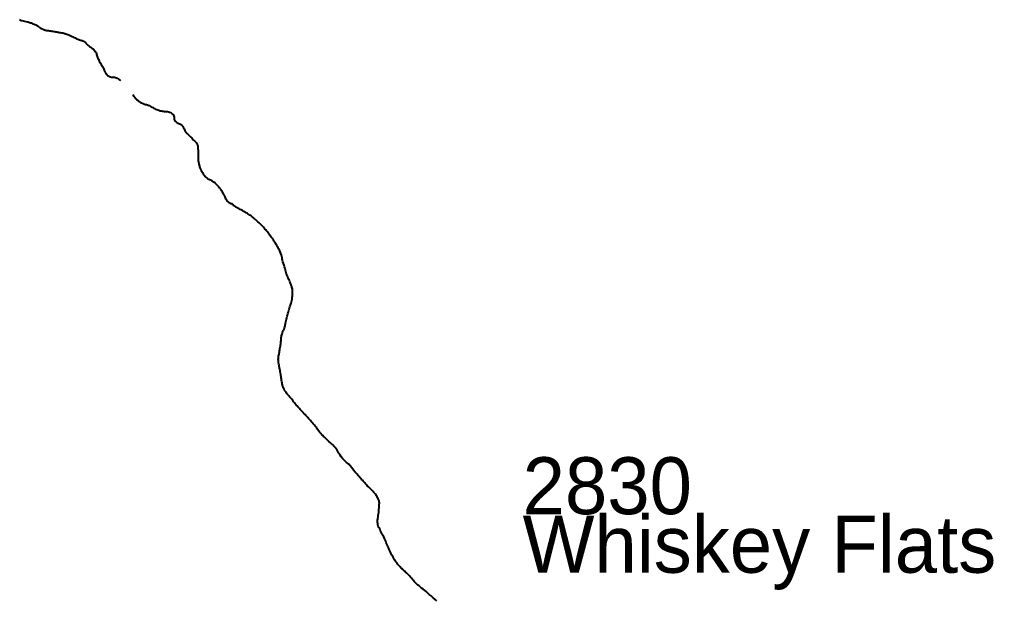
# Model space of a CAD drawing. Extents: x 322505 to 642419, y 5806860 to 5919753.
# Drawn here: x 604345 to 610335, y 5874702 to 5878274 of the extents above; entities that cross this region are included whole.
import ezdxf

# ---------------------------------------------------------------- set-up
doc = ezdxf.new("R2010")
doc.units = 0
doc.header["$LTSCALE"] = 140
for name, color, linetype, lineweight in [('1', 7, 'Continuous', 40), ('4', 7, 'Continuous', 40), ('5', 7, 'Continuous', 40)]:
    doc.layers.add(name, color=color, linetype=linetype, lineweight=lineweight)

msp = doc.modelspace()

# ---------------------------------------------------------------- linework, layer by layer
at = {"layer": '4'}
msp.add_lwpolyline([(604345, 5878274), (604349, 5878271), (604352, 5878270), (604356, 5878268), (604359.5, 5878267)], dxfattribs=at)
at = {"layer": '5'}
for points in [[(604360, 5878267), (604392, 5878260), (604395, 5878259), (604399, 5878259), (604403, 5878258), (604407, 5878256), (604413, 5878254), (604418, 5878253), (604422, 5878251), (604426, 5878250), (604430, 5878248), (604435, 5878246), (604440, 5878244), (604445, 5878241), (604451, 5878238), (604456, 5878234), (604459, 5878232), (604464, 5878228), (604469, 5878225), (604474, 5878221), (604480, 5878218), (604485, 5878216), (604490, 5878213), (604494, 5878212), (604498, 5878210), (604502, 5878209), (604507, 5878208), (604513, 5878207), (604519, 5878207), (604524, 5878206), (604530, 5878205), (604537, 5878204), (604543, 5878203), (604549, 5878202), (604556, 5878201), (604563, 5878200), (604569, 5878199), (604575, 5878198), (604580, 5878197), (604584, 5878196), (604589, 5878195), (604595, 5878194), (604603, 5878192), (604611, 5878191), (604618, 5878189), (604619, 5878188.5)], [(604619, 5878188.5), (604626, 5878187), (604631, 5878185), (604637, 5878183), (604643, 5878182), (604649, 5878179), (604656, 5878176), (604665, 5878172), (604673, 5878168), (604680, 5878164), (604687, 5878161), (604693, 5878158), (604698, 5878155), (604703, 5878153), (604709, 5878151), (604714, 5878149), (604720, 5878147), (604724, 5878146), (604727, 5878145), (604731, 5878144), (604735, 5878142), (604739, 5878140), (604745, 5878136), (604750, 5878132), (604754, 5878128), (604758, 5878124), (604761, 5878121), (604764, 5878118), (604768, 5878114), (604773, 5878110), (604778, 5878106), (604782, 5878103), (604788, 5878100), (604793, 5878096), (604798, 5878093), (604803, 5878089), (604807, 5878083), (604811, 5878078), (604813, 5878073), (604816, 5878068), (604818, 5878063), (604819, 5878059), (604821, 5878053), (604823, 5878047), (604825, 5878041), (604827, 5878036), (604830, 5878030), (604833, 5878024), (604836, 5878018), (604840, 5878012), (604844, 5878006), (604848, 5877998), (604852, 5877991), (604856, 5877985), (604858, 5877979), (604861, 5877974), (604863, 5877968), (604866, 5877962), (604869, 5877956), (604872, 5877949), (604876, 5877943), (604880, 5877937), (604883, 5877933), (604887, 5877930), (604891, 5877927), (604897, 5877924), (604904, 5877922), (604911, 5877920), (604918, 5877919), (604924, 5877919), (604930, 5877919), (604935, 5877918), (604941, 5877916), (604946, 5877913), (604952, 5877910), (604957, 5877906), (604962, 5877902), (604966, 5877898)], [(605041.8, 5877812.5), (605045, 5877808), (605048, 5877803), (605051, 5877798), (605054, 5877794), (605057, 5877790), (605060, 5877788), (605062, 5877785), (605065, 5877783), (605068, 5877780), (605072, 5877778), (605075, 5877774), (605079, 5877771), (605084, 5877767), (605089, 5877764), (605096, 5877761), (605105, 5877757), (605113, 5877754), (605120, 5877752), (605126, 5877751), (605132, 5877749), (605137, 5877747), (605143, 5877745), (605149, 5877742), (605155, 5877738), (605161, 5877735), (605167, 5877732), (605171, 5877728), (605177, 5877726), (605182, 5877723), (605189, 5877720), (605196, 5877718), (605201, 5877716), (605206, 5877714), (605211, 5877713), (605216, 5877712), (605220, 5877712), (605225, 5877711), (605231, 5877710), (605237, 5877709), (605242, 5877709), (605249, 5877709), (605255, 5877708), (605262, 5877707), (605268, 5877705), (605275, 5877702), (605280, 5877699), (605284, 5877695), (605288, 5877692), (605291, 5877689), (605293, 5877686), (605294, 5877683), (605295, 5877680), (605296, 5877673), (605297, 5877665), (605297, 5877660), (605299, 5877656), (605301, 5877652), (605305, 5877648), (605309, 5877644), (605312, 5877641), (605315, 5877639), (605318, 5877637), (605321, 5877636), (605325, 5877635), (605329, 5877633), (605332, 5877632), (605336, 5877630), (605340, 5877628), (605343, 5877625), (605346, 5877621), (605349, 5877617), (605351, 5877613), (605354, 5877607), (605357, 5877602), (605359, 5877597), (605361, 5877593), (605362, 5877589), (605364, 5877586), (605367, 5877582), (605371, 5877578), (605375, 5877573), (605380, 5877569), (605384, 5877564), (605389, 5877560), (605394, 5877555), (605399, 5877551), (605404, 5877546), (605410, 5877540), (605416, 5877533), (605421, 5877528), (605426, 5877523), (605431, 5877518), (605434, 5877513), (605437, 5877510), (605438, 5877505), (605440, 5877501), (605441, 5877496), (605442, 5877492), (605442, 5877479), (605443, 5877470)], [(605443, 5877470), (605443, 5877464), (605443, 5877458), (605443, 5877451), (605443, 5877445), (605443, 5877437), (605443, 5877429), (605443, 5877422), (605444, 5877414), (605444, 5877408), (605444, 5877403), (605445, 5877399), (605445, 5877395), (605447, 5877390), (605448, 5877384), (605449, 5877379), (605451, 5877373), (605453, 5877368), (605454, 5877363), (605457, 5877358), (605459, 5877353), (605463, 5877346), (605466, 5877340), (605470, 5877334), (605473, 5877329), (605475, 5877325), (605478, 5877320), (605482, 5877314), (605487, 5877309), (605493, 5877303), (605499, 5877298), (605504, 5877295), (605509, 5877293), (605514, 5877290), (605519, 5877288), (605525, 5877285), (605529, 5877282), (605534, 5877279), (605538, 5877277), (605541, 5877274), (605544, 5877273), (605547, 5877270), (605551, 5877266), (605555, 5877262), (605560, 5877256), (605564, 5877252), (605568, 5877247), (605572, 5877242), (605576, 5877238), (605580, 5877233), (605584, 5877228), (605588, 5877222), (605592, 5877215), (605595, 5877209), (605598, 5877203), (605600, 5877199), (605602, 5877195), (605605, 5877190), (605607, 5877184), (605610, 5877178), (605613, 5877172), (605615, 5877168), (605618, 5877164), (605620, 5877160), (605624, 5877157), (605628, 5877153), (605631, 5877151), (605635, 5877148), (605638, 5877146), (605641, 5877145), (605644, 5877143), (605647, 5877142), (605652, 5877143)], [(605865, 5876974), (605860, 5876981), (605854, 5876986), (605850, 5876992), (605845, 5876997), (605839, 5877003), (605834, 5877009), (605827, 5877016), (605819, 5877023), (605811, 5877031), (605803, 5877038), (605796, 5877044), (605790, 5877049), (605782, 5877056), (605776, 5877061), (605769, 5877066), (605762, 5877071), (605756, 5877075), (605750, 5877079), (605745, 5877083), (605739, 5877086), (605732, 5877090), (605725, 5877094), (605716, 5877099), (605709, 5877103), (605702, 5877106), (605696, 5877109), (605691, 5877112), (605685, 5877115), (605681, 5877118), (605676, 5877121), (605669, 5877126), (605663, 5877129), (605661, 5877132), (605658, 5877135), (605655, 5877138), (605652, 5877143)], [(605956, 5876324), (605957, 5876329), (605958, 5876335), (605960, 5876342), (605963, 5876350), (605964, 5876355), (605966, 5876359), (605968, 5876363), (605970, 5876367), (605972, 5876371), (605974, 5876378), (605976, 5876385), (605978, 5876391), (605979, 5876397), (605980, 5876402), (605981, 5876408), (605983, 5876415), (605985, 5876423), (605987, 5876432), (605989, 5876442), (605991, 5876450), (605994, 5876457), (605995, 5876464), (605998, 5876470), (606000, 5876477), (606002, 5876485), (606004, 5876493), (606006, 5876500), (606008, 5876507), (606010, 5876513), (606011, 5876517), (606013, 5876523), (606015, 5876530), (606018, 5876538), (606019, 5876546), (606021, 5876554), (606021, 5876560), (606022, 5876566), (606023, 5876572), (606023, 5876578), (606023, 5876584), (606023, 5876590), (606024, 5876596), (606024, 5876601), (606024, 5876605), (606024, 5876613), (606023, 5876617), (606022, 5876622), (606020, 5876628), (606019, 5876632), (606017, 5876636), (606016, 5876639), (606015, 5876643), (606014, 5876646), (606011, 5876654), (606008, 5876662), (606005, 5876669), (606002, 5876675), (606000, 5876680), (605998, 5876685), (605995, 5876690), (605992, 5876697), (605989, 5876705), (605985, 5876714), (605982, 5876725), (605980, 5876733), (605978, 5876740), (605976, 5876747), (605974, 5876754), (605972, 5876763), (605968, 5876774), (605965, 5876784), (605963, 5876793), (605961, 5876802), (605960, 5876809), (605958, 5876817), (605956, 5876826), (605953, 5876835), (605949, 5876846), (605944, 5876856), (605940, 5876863), (605936, 5876871), (605932, 5876877), (605927, 5876884), (605924, 5876890), (605921, 5876895), (605918, 5876901), (605916, 5876905), (605913, 5876910), (605910, 5876914), (605907, 5876918), (605903, 5876924), (605899, 5876929), (605893, 5876936), (605889, 5876942), (605885, 5876948), (605882, 5876953), (605878, 5876957), (605875, 5876962), (605870, 5876968), (605865, 5876974)], [(606226, 5875700), (606220, 5875706), (606215, 5875711), (606210, 5875716), (606205, 5875721), (606198, 5875729), (606192, 5875736), (606186, 5875744), (606180, 5875751), (606175, 5875758), (606173, 5875761), (606169, 5875767), (606164, 5875773), (606159, 5875780), (606151, 5875789), (606145, 5875796), (606139, 5875803), (606134, 5875809), (606129, 5875815), (606123, 5875821), (606118, 5875827), (606112, 5875833), (606106, 5875840), (606101, 5875845), (606096, 5875850), (606093, 5875853), (606090, 5875857), (606087, 5875860), (606083, 5875865), (606078, 5875870), (606071, 5875877), (606066, 5875882), (606061, 5875888), (606056, 5875892), (606052, 5875898), (606047, 5875904), (606041, 5875911), (606036, 5875918), (606031, 5875924), (606028, 5875928), (606024, 5875933), (606019, 5875939), (606013, 5875946), (606007, 5875953), (606001, 5875960), (605994, 5875969), (605988, 5875976), (605984, 5875982), (605980, 5875987), (605975, 5875994), (605972, 5876001), (605969, 5876008), (605966, 5876014), (605964, 5876020), (605963, 5876024), (605962, 5876028), (605961, 5876034), (605960, 5876040), (605958, 5876047), (605957, 5876056), (605956, 5876065), (605955, 5876072), (605954, 5876079), (605953, 5876085), (605952, 5876091), (605950, 5876099), (605949, 5876108), (605948, 5876116), (605946, 5876124), (605945, 5876130), (605944, 5876135), (605942, 5876141), (605941, 5876148), (605939, 5876155), (605938, 5876163), (605938, 5876169), (605937, 5876174), (605937, 5876179), (605936, 5876184), (605937, 5876189), (605937, 5876197), (605938, 5876204), (605940, 5876211), (605941, 5876217), (605942, 5876222), (605943, 5876226), (605944, 5876231), (605945, 5876238), (605946, 5876244), (605947, 5876252), (605949, 5876260), (605950, 5876267), (605951, 5876273), (605952, 5876278), (605952, 5876284), (605953, 5876292), (605954, 5876299), (605955, 5876307), (605955, 5876313), (605955, 5876319), (605956, 5876324)], [(606611, 5875033), (606608, 5875040), (606604, 5875049), (606600, 5875057), (606597, 5875066), (606593, 5875075), (606589, 5875084), (606585, 5875093), (606582, 5875099), (606579, 5875105), (606576, 5875111), (606572, 5875118), (606568, 5875126), (606564, 5875135), (606560, 5875142), (606556, 5875148), (606553, 5875154), (606551, 5875160), (606549, 5875167), (606548, 5875173), (606548, 5875178), (606547, 5875182), (606547, 5875188), (606547, 5875192), (606547, 5875197), (606548, 5875202), (606549, 5875209), (606550, 5875217), (606551, 5875226), (606552, 5875235), (606554, 5875243), (606554, 5875250), (606555, 5875257), (606555, 5875263), (606556, 5875271), (606556, 5875279), (606557, 5875287), (606557, 5875294), (606558, 5875299), (606558, 5875303), (606557, 5875308), (606556, 5875314), (606554, 5875320), (606551, 5875327), (606547, 5875334), (606544, 5875340), (606541, 5875346), (606538, 5875350), (606535, 5875355), (606530, 5875361), (606525, 5875366), (606520, 5875372), (606515, 5875377), (606511, 5875381), (606507, 5875385), (606502, 5875390), (606497, 5875395), (606491, 5875401), (606484, 5875408), (606478, 5875414), (606473, 5875420), (606468, 5875425), (606464, 5875430), (606459, 5875435), (606454, 5875441), (606449, 5875447), (606444, 5875453), (606438, 5875459), (606434, 5875464), (606430, 5875468), (606425, 5875473), (606421, 5875479), (606416, 5875484), (606409, 5875491), (606399, 5875504), (606389, 5875518), (606379, 5875530), (606370, 5875540), (606362, 5875547), (606356, 5875551), (606350, 5875557), (606346, 5875561), (606342, 5875565), (606333, 5875574), (606324, 5875585), (606317, 5875595), (606312, 5875604), (606307, 5875611), (606303, 5875619), (606298, 5875627), (606292, 5875635), (606286, 5875643), (606279, 5875650), (606273, 5875657), (606269, 5875662), (606264, 5875666), (606258, 5875672), (606250, 5875678), (606242, 5875686), (606233, 5875694), (606226, 5875700)], [(606911, 5874701), (606901, 5874709), (606889, 5874719), (606885, 5874722), (606876, 5874730), (606864, 5874740), (606854, 5874749), (606845, 5874757), (606836, 5874765), (606828, 5874771), (606818, 5874779), (606810, 5874786), (606802, 5874792), (606795, 5874797), (606791, 5874800), (606786, 5874804), (606780, 5874811), (606772, 5874819), (606768, 5874825), (606764, 5874829), (606756, 5874839), (606750, 5874846), (606745, 5874851), (606740, 5874857), (606736, 5874862), (606731, 5874867), (606725, 5874872), (606719, 5874877), (606714, 5874882), (606709, 5874887), (606706.1, 5874889), (606704, 5874890), (606700, 5874893), (606696, 5874898), (606690, 5874903), (606685, 5874909), (606679, 5874915), (606674, 5874921), (606670, 5874926), (606667, 5874931), (606663, 5874935), (606660, 5874940), (606656, 5874947), (606652, 5874953), (606648, 5874960), (606644, 5874965), (606642, 5874969), (606639, 5874974), (606635, 5874981), (606631, 5874989), (606626, 5874999), (606621, 5875011), (606616, 5875022), (606614, 5875026), (606611, 5875033)]]:
    msp.add_lwpolyline(points, dxfattribs=at)

# ---------------------------------------------------------------- texts
at = {"layer": '1'}
for s, p in [('2830', (607439.1, 5875232.8)), ('Whiskey Flats', (607439.1, 5874872.8))]:
    msp.add_text(s, height=350, dxfattribs=at).set_placement(p)

doc.saveas('drawing.dxf')
